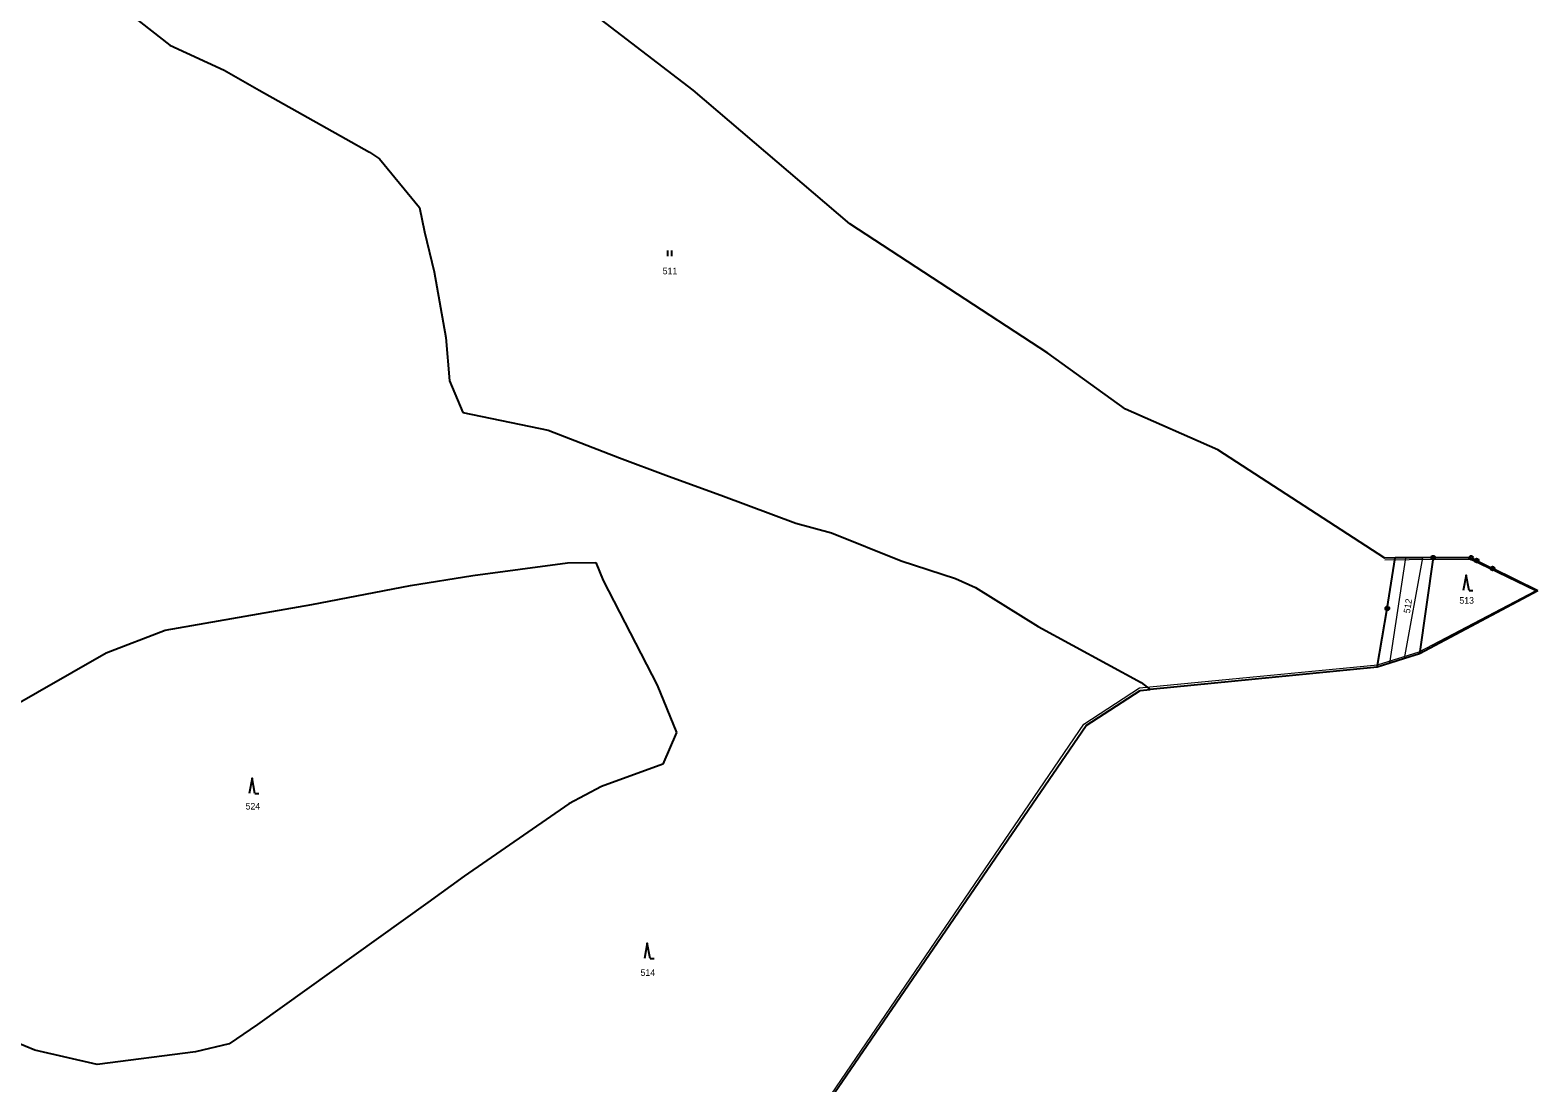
# Model space of a CAD drawing. Extents: x -653193 to -651624, y -1092017 to -1090260.
# Drawn here: x -652015.8 to -651623.6, y -1091135.1 to -1090861.4 of the extents above; entities that cross this region are included whole.
import ezdxf
from ezdxf.enums import TextEntityAlignment as Align

# ---------------------------------------------------------------- set-up
doc = ezdxf.new("R2010")
doc.units = 0
doc.header["$LTSCALE"] = 0.68
for name, color, linetype, lineweight in [('1', 7, 'Continuous', 25), ('3', 7, 'Continuous', 25), ('4', 7, 'Continuous', 13), ('8', 7, 'Continuous', 25)]:
    doc.layers.add(name, color=color, linetype=linetype, lineweight=lineweight)
doc.layers.add('2', color=7, linetype='Continuous')

msp = doc.modelspace()

# ---------------------------------------------------------------- linework, layer by layer
at = {"layer": '1'}
for p, q in [((-652003.19, -1090846.74), (-651979.53, -1090865.27)), ((-651843.37, -1090877.04), (-651879.63, -1090849.15)), ((-651979.53, -1090865.27), (-651965.35, -1090871.83)), ((-651965.35, -1090871.83), (-651956.23, -1090876.99)), ((-651956.23, -1090876.99), (-651933.72, -1090889.69)), ((-651802.58, -1090911.78), (-651843.37, -1090877.04)), ((-651933.72, -1090889.69), (-651927.55, -1090893.11)), ((-651927.55, -1090893.11), (-651924.96, -1090894.88)), ((-651924.96, -1090894.88), (-651914.49, -1090907.5)), ((-651914.49, -1090907.5), (-651913.21, -1090913.85)), ((-651913.21, -1090913.85), (-651910.73, -1090924.19)), ((-651751.03, -1090945.4), (-651802.58, -1090911.78)), ((-651910.73, -1090924.19), (-651907.67, -1090941.33)), ((-651907.67, -1090941.33), (-651906.76, -1090952.58)), ((-651730.86, -1090959.97), (-651751.03, -1090945.4)), ((-651906.76, -1090952.58), (-651903.22, -1090960.83)), ((-651903.22, -1090960.83), (-651881.1, -1090965.43)), ((-651706.87, -1090970.5), (-651730.86, -1090959.97)), ((-651881.1, -1090965.43), (-651862.52, -1090972.55)), ((-651862.52, -1090972.55), (-651850.46, -1090977.09)), ((-651663.41, -1090998.64), (-651706.87, -1090970.5)), ((-651850.46, -1090977.09), (-651835.47, -1090982.52)), ((-651835.47, -1090982.52), (-651816.62, -1090989.58)), ((-651816.62, -1090989.58), (-651807.32, -1090992.12)), ((-651807.32, -1090992.12), (-651789.21, -1090999.41)), ((-651900.7, -1091003.17), (-651875.99, -1090999.9)), ((-651875.99, -1090999.9), (-651868.68, -1090999.83)), ((-651868.68, -1090999.83), (-651866.75, -1091004.51)), ((-651789.21, -1090999.41), (-651775.04, -1091003.93)), ((-651660.69, -1090998.62), (-651663.41, -1090998.64)), ((-651662.74, -1091011.74), (-651660.69, -1090998.62)), ((-651657.88, -1090998.6), (-651660.69, -1090998.62)), ((-651653.48, -1090998.56), (-651657.88, -1090998.6)), ((-651650.81, -1090998.54), (-651654.35, -1091023.53)), ((-651650.81, -1090998.54), (-651653.48, -1090998.56)), ((-651640.94, -1090998.57), (-651650.81, -1090998.54)), ((-651640.94, -1090998.57), (-651639.49, -1090999.29)), ((-651639.49, -1090999.29), (-651635.34, -1091001.35)), ((-651916.88, -1091005.82), (-651900.7, -1091003.17)), ((-651775.04, -1091003.93), (-651769.89, -1091006.3)), ((-651623.57, -1091007.18), (-651635.34, -1091001.35)), ((-651942.54, -1091010.75), (-651916.88, -1091005.82)), ((-651866.75, -1091004.51), (-651852.66, -1091031.7)), ((-651769.89, -1091006.3), (-651753.53, -1091016.43)), ((-651623.57, -1091007.18), (-651654.35, -1091023.53)), ((-651980.72, -1091017.41), (-651942.54, -1091010.75)), ((-651665.41, -1091026.99), (-651662.74, -1091011.74)), ((-651996.02, -1091023.32), (-651980.72, -1091017.41)), ((-651753.53, -1091016.43), (-651726.79, -1091030.97)), ((-652022.86, -1091038.65), (-651996.02, -1091023.32)), ((-651654.35, -1091023.53), (-651658.29, -1091024.76)), ((-651665.41, -1091026.99), (-651724.41, -1091032.79)), ((-651662.05, -1091025.94), (-651665.41, -1091026.99)), ((-651658.29, -1091024.76), (-651662.05, -1091025.94)), ((-651852.66, -1091031.7), (-651847.69, -1091044)), ((-651726.79, -1091030.97), (-651724.41, -1091032.79)), ((-651741.09, -1091042.17), (-651727.06, -1091033.05)), ((-651727.06, -1091033.05), (-651724.41, -1091032.79)), ((-651813.51, -1091147.74), (-651741.09, -1091042.17)), ((-651847.69, -1091044), (-651851.21, -1091052.27)), ((-651851.21, -1091052.27), (-651867.2, -1091058.03)), ((-651867.2, -1091058.03), (-651875.69, -1091062.58)), ((-651875.69, -1091062.58), (-651902.91, -1091081.38)), ((-651902.91, -1091081.38), (-651912.33, -1091088.17)), ((-651912.33, -1091088.17), (-651956.7, -1091119.96)), ((-651956.7, -1091119.96), (-651964.07, -1091124.98)), ((-652014.63, -1091126.63), (-652025.24, -1091122.2)), ((-651964.07, -1091124.98), (-651972.8, -1091127)), ((-651998.37, -1091130.28), (-652014.63, -1091126.63)), ((-651972.8, -1091127), (-651998.37, -1091130.28))]:
    msp.add_line(p, q, dxfattribs=at)
at = {"layer": '3'}
for p, q in [((-651849.911, -1090920.2), (-651849.911, -1090918.7)), ((-651848.91, -1090920.2), (-651848.91, -1090918.7)), ((-651641.47, -1091007.11), (-651640.474, -1091007.11)), ((-651957.34, -1091059.9), (-651956.344, -1091059.9)), ((-651854.51, -1091102.78), (-651853.514, -1091102.78))]:
    msp.add_line(p, q, dxfattribs=at)
for points in [[(-651641.47, -1091007.11), (-651642.22, -1091003.11), (-651642.97, -1091007.11)], [(-651957.34, -1091059.9), (-651958.09, -1091055.9), (-651958.84, -1091059.9)], [(-651854.51, -1091102.78), (-651855.26, -1091098.78), (-651856.01, -1091102.78)]]:
    msp.add_lwpolyline(points, dxfattribs=at)
at = {"layer": '4'}
for p, q in [((-651662.05, -1091025.94), (-651657.88, -1090998.6)), ((-651658.29, -1091024.76), (-651653.48, -1090998.56))]:
    msp.add_line(p, q, dxfattribs=at)
msp.add_lwpolyline([(-652035, -1091341.19), (-651992.17, -1091317.02), (-651966.06, -1091276.8), (-651951.26, -1091267.39), (-651935.12, -1091262.33), (-651908.39, -1091243.89), (-651856.64, -1091190.48), (-651819.93, -1091150.64), (-651813.86, -1091147.54), (-651741.68, -1091041.82), (-651727.21, -1091032.36), (-651665.25, -1091026.44), (-651654.46, -1091023), (-651624.19, -1091007.19), (-651641.09, -1090999.02), (-651650.73, -1090999.02), (-651663.38, -1090999.21)], dxfattribs=at)
at = {"layer": '8'}
for centre, radius in [((-651650.81, -1090998.5399), 0.5), ((-651650.81, -1090998.5399), 0.0303), ((-651640.94, -1090998.5699), 0.5), ((-651640.94, -1090998.5699), 0.0303), ((-651639.49, -1090999.2899), 0.5), ((-651639.49, -1090999.2899), 0.0303), ((-651635.34, -1091001.3499), 0.5), ((-651635.34, -1091001.3499), 0.0303), ((-651662.74, -1091011.7399), 0.5), ((-651662.74, -1091011.7399), 0.0303)]:
    msp.add_circle(centre, radius, dxfattribs=at)

# ---------------------------------------------------------------- texts
at = {"layer": '2'}
for s, p in [('511', (-651849.359, -1090924.865)), ('513', (-651642.089, -1091010.515)), ('524', (-651957.889, -1091064.025)), ('514', (-651855.129, -1091107.275))]:
    msp.add_text(s, height=1.7, dxfattribs=at).set_placement(p, align=Align.CENTER)
msp.add_text('512', height=1.7, rotation=81, dxfattribs=at).set_placement((-651656.5595, -1091011.239), align=Align.CENTER)

doc.saveas('drawing.dxf')
